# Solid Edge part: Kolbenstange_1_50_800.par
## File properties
Username: ahadarics
Dokumentum tartalom típus: 0
Author: ahadarics
Last saved by: ahadarics
Revision: 92
Sűrűség: 0,000 kg/m^3
Pontosság: 0,990
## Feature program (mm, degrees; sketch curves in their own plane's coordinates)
base feature "unnamed BaseFeature 1"
thread "unnamed Thread 1"
chamfer "Letörés_1"  SetBackValue2 = 20 deg
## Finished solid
Body 1: solid body, 21 faces, 32 edges, 14 vertices.
  Faces by surface: plane 8, cylinder 5, cone 4, torus 4
  Edges by curve: circle 17, line 9, curve on surface 4, ellipse 2
Bounding box of the edges (mm; curved faces can reach further): 50.000 x 50.000 x 944.000, from (-25, -25, -86.5) to (25, 25, 857.5).
Cylindrical faces by radius (mm): R6.75 x1, R8 x1, R9.75 x1, R10 x1, R25 x1
Conical faces (half-angle, radius in mm at the cone's reference point): 20 deg R8 x1, 30 deg R9.875 x1, 45 deg R24.25 x1, 60 deg R7.375 x1
Toroidal faces (ring radius, tube radius in mm): R7.15 r0.4 x2, R8.55 r1.2 x2
Planar faces by outward normal: +x 1, +z 3, -x 1, -z 1, oblique 2
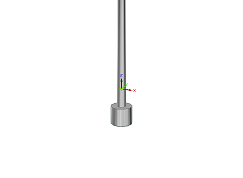
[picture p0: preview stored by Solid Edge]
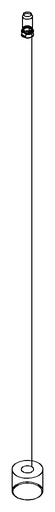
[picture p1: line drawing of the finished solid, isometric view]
